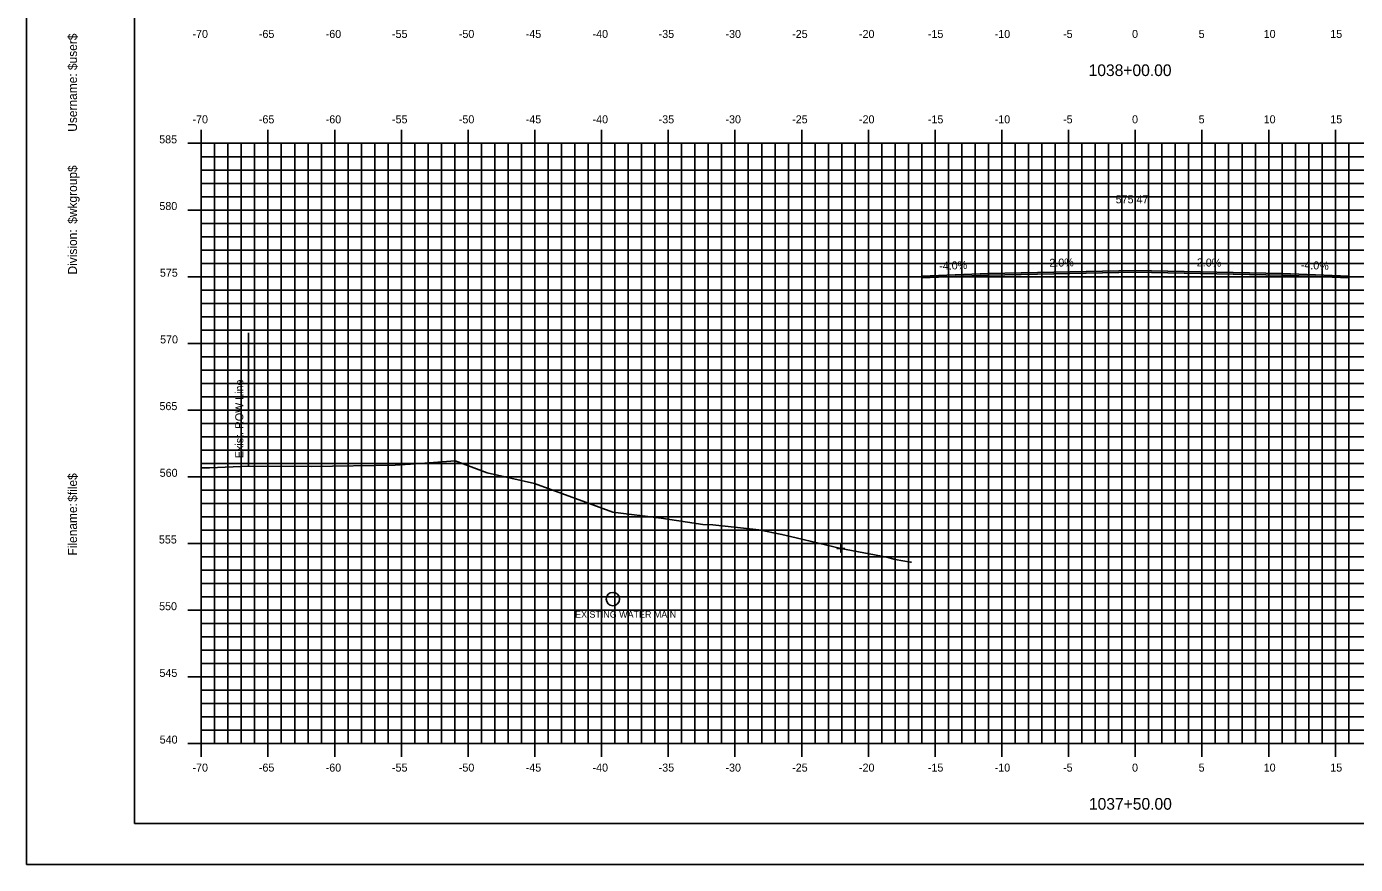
# Model space of a CAD drawing. Extents: x 1060781 to 1060951, y 779716 to 779826.
# Drawn here: x 1060780.7 to 1060880.3, y 779715.6 to 779778.5 of the extents above; entities that cross this region are included whole.
import ezdxf

# ---------------------------------------------------------------- set-up
doc = ezdxf.new("R2010")
doc.units = 0
for name, color, linetype in [('ANNOTATION', 7, 'Continuous'), ('BORDER', 7, 'Continuous'), ('D_Roadway_Centerline', 7, 'Continuous'), ('D_Roadway_Centerline_Text', 7, 'Continuous'), ('D_Roadway_Edge_TW_Mill_Overlay', 7, 'Continuous'), ('D_Text_Monospaced', 7, 'Continuous'), ('E_ROW_Line', 7, 'Continuous'), ('Existing Water Main', 7, 'Continuous'), ('H_V ANNOTATION', 7, 'Continuous'), ('MAJOR', 7, 'Continuous'), ('MINOR', 7, 'Continuous'), ('PLOT BOUNDARY', 7, 'Continuous'), ('S_Roadway_Centerline', 7, 'Continuous'), ('S_Wetland_RiverineUnconsSubstr', 7, 'Continuous')]:
    doc.layers.add(name, color=color, linetype=linetype)

msp = doc.modelspace()

# ---------------------------------------------------------------- linework, layer by layer
at = {"layer": 'BORDER'}
msp.add_lwpolyline([(1060788.836, 779718.706), (1060948.836, 779718.706), (1060948.836, 779823.706), (1060788.836, 779823.706)], close=True, dxfattribs=at)
at = {"layer": 'D_Roadway_Centerline'}
msp.add_lwpolyline([(1060847.836, 779759.756), (1060852.836, 779759.956), (1060863.836, 779760.176), (1060874.836, 779759.956), (1060879.836, 779759.756)], dxfattribs=at)
at = {"layer": 'D_Roadway_Edge_TW_Mill_Overlay'}
msp.add_lwpolyline([(1060863.836, 779760.176), (1060874.836, 779759.956), (1060879.836, 779759.756), (1060879.836, 779759.631), (1060874.836, 779759.831), (1060863.836, 779760.051), (1060852.836, 779759.831), (1060847.836, 779759.631), (1060847.836, 779759.756), (1060852.836, 779759.956)], close=True, dxfattribs=at)
at = {"layer": 'E_ROW_Line'}
msp.add_line((1060797.383, 779745.511), (1060797.383, 779755.511), dxfattribs=at)
msp.add_line((1060797.383, 779745.511), (1060797.383, 779755.511), dxfattribs=at)
at = {"layer": 'Existing Water Main'}
msp.add_lwpolyline([(1060824.687, 779735.541), (1060824.687, 779735.541)], dxfattribs=at)
msp.add_circle((1060824.687, 779735.541), 0.501, dxfattribs=at)
at = {"layer": 'MAJOR'}
for p, q in [((1060793.836, 779770.708), (1060793.836, 779769.706)), ((1060798.836, 779770.708), (1060798.836, 779769.706)), ((1060803.836, 779770.708), (1060803.836, 779769.706)), ((1060808.836, 779770.708), (1060808.836, 779769.706)), ((1060813.836, 779770.708), (1060813.836, 779769.706)), ((1060818.836, 779770.708), (1060818.836, 779769.706)), ((1060823.836, 779770.708), (1060823.836, 779769.706)), ((1060828.836, 779770.708), (1060828.836, 779769.706)), ((1060833.836, 779770.708), (1060833.836, 779769.706)), ((1060838.836, 779770.708), (1060838.836, 779769.706)), ((1060843.836, 779770.708), (1060843.836, 779769.706)), ((1060848.836, 779770.708), (1060848.836, 779769.706)), ((1060853.836, 779770.708), (1060853.836, 779769.706)), ((1060858.836, 779770.708), (1060858.836, 779769.706)), ((1060863.836, 779770.708), (1060863.836, 779769.706)), ((1060868.836, 779770.708), (1060868.836, 779769.706)), ((1060873.836, 779770.708), (1060873.836, 779769.706)), ((1060878.836, 779770.708), (1060878.836, 779769.706)), ((1060792.834, 779769.706), (1060793.836, 779769.706)), ((1060793.836, 779769.706), (1060933.836, 779769.706)), ((1060793.836, 779724.706), (1060793.836, 779769.706)), ((1060793.836, 779724.706), (1060793.836, 779769.706)), ((1060793.836, 779769.706), (1060933.836, 779769.706)), ((1060798.836, 779724.706), (1060798.836, 779769.706)), ((1060803.836, 779724.706), (1060803.836, 779769.706)), ((1060808.836, 779724.706), (1060808.836, 779769.706)), ((1060813.836, 779724.706), (1060813.836, 779769.706)), ((1060818.836, 779724.706), (1060818.836, 779769.706)), ((1060823.836, 779724.706), (1060823.836, 779769.706)), ((1060828.836, 779724.706), (1060828.836, 779769.706)), ((1060833.836, 779724.706), (1060833.836, 779769.706)), ((1060838.836, 779724.706), (1060838.836, 779769.706)), ((1060843.836, 779724.706), (1060843.836, 779769.706)), ((1060848.836, 779724.706), (1060848.836, 779769.706)), ((1060853.836, 779724.706), (1060853.836, 779769.706)), ((1060858.836, 779724.706), (1060858.836, 779769.706)), ((1060863.836, 779724.706), (1060863.836, 779769.706)), ((1060868.836, 779724.706), (1060868.836, 779769.706)), ((1060873.836, 779724.706), (1060873.836, 779769.706)), ((1060878.836, 779724.706), (1060878.836, 779769.706)), ((1060792.834, 779764.706), (1060793.836, 779764.706)), ((1060793.836, 779764.706), (1060933.836, 779764.706)), ((1060792.834, 779759.706), (1060793.836, 779759.706)), ((1060793.836, 779759.706), (1060933.836, 779759.706)), ((1060792.834, 779754.706), (1060793.836, 779754.706)), ((1060793.836, 779754.706), (1060933.836, 779754.706)), ((1060792.834, 779749.706), (1060793.836, 779749.706)), ((1060793.836, 779749.706), (1060933.836, 779749.706)), ((1060792.834, 779744.706), (1060793.836, 779744.706)), ((1060793.836, 779744.706), (1060933.836, 779744.706)), ((1060792.834, 779739.706), (1060793.836, 779739.706)), ((1060793.836, 779739.706), (1060933.836, 779739.706)), ((1060792.834, 779734.706), (1060793.836, 779734.706)), ((1060793.836, 779734.706), (1060933.836, 779734.706)), ((1060792.834, 779729.706), (1060793.836, 779729.706)), ((1060793.836, 779729.706), (1060933.836, 779729.706)), ((1060792.834, 779724.706), (1060793.836, 779724.706)), ((1060793.836, 779724.706), (1060933.836, 779724.706)), ((1060793.836, 779724.706), (1060933.836, 779724.706)), ((1060793.836, 779723.704), (1060793.836, 779724.706)), ((1060798.836, 779723.704), (1060798.836, 779724.706)), ((1060803.836, 779723.704), (1060803.836, 779724.706)), ((1060808.836, 779723.704), (1060808.836, 779724.706)), ((1060813.836, 779723.704), (1060813.836, 779724.706)), ((1060818.836, 779723.704), (1060818.836, 779724.706)), ((1060823.836, 779723.704), (1060823.836, 779724.706)), ((1060828.836, 779723.704), (1060828.836, 779724.706)), ((1060833.836, 779723.704), (1060833.836, 779724.706)), ((1060838.836, 779723.704), (1060838.836, 779724.706)), ((1060843.836, 779723.704), (1060843.836, 779724.706)), ((1060848.836, 779723.704), (1060848.836, 779724.706)), ((1060853.836, 779723.704), (1060853.836, 779724.706)), ((1060858.836, 779723.704), (1060858.836, 779724.706)), ((1060863.836, 779723.704), (1060863.836, 779724.706)), ((1060868.836, 779723.704), (1060868.836, 779724.706)), ((1060873.836, 779723.704), (1060873.836, 779724.706)), ((1060878.836, 779723.704), (1060878.836, 779724.706))]:
    msp.add_line(p, q, dxfattribs=at)
at = {"layer": 'MINOR'}
for p, q in [((1060794.836, 779724.706), (1060794.836, 779769.706)), ((1060795.836, 779724.706), (1060795.836, 779769.706)), ((1060796.836, 779724.706), (1060796.836, 779769.706)), ((1060797.836, 779724.706), (1060797.836, 779769.706)), ((1060799.836, 779724.706), (1060799.836, 779769.706)), ((1060800.836, 779724.706), (1060800.836, 779769.706)), ((1060801.836, 779724.706), (1060801.836, 779769.706)), ((1060802.836, 779724.706), (1060802.836, 779769.706)), ((1060804.836, 779724.706), (1060804.836, 779769.706)), ((1060805.836, 779724.706), (1060805.836, 779769.706)), ((1060806.836, 779724.706), (1060806.836, 779769.706)), ((1060807.836, 779724.706), (1060807.836, 779769.706)), ((1060809.836, 779724.706), (1060809.836, 779769.706)), ((1060810.836, 779724.706), (1060810.836, 779769.706)), ((1060811.836, 779724.706), (1060811.836, 779769.706)), ((1060812.836, 779724.706), (1060812.836, 779769.706)), ((1060814.836, 779724.706), (1060814.836, 779769.706)), ((1060815.836, 779724.706), (1060815.836, 779769.706)), ((1060816.836, 779724.706), (1060816.836, 779769.706)), ((1060817.836, 779724.706), (1060817.836, 779769.706)), ((1060819.836, 779724.706), (1060819.836, 779769.706)), ((1060820.836, 779724.706), (1060820.836, 779769.706)), ((1060821.836, 779724.706), (1060821.836, 779769.706)), ((1060822.836, 779724.706), (1060822.836, 779769.706)), ((1060824.836, 779724.706), (1060824.836, 779769.706)), ((1060825.836, 779724.706), (1060825.836, 779769.706)), ((1060826.836, 779724.706), (1060826.836, 779769.706)), ((1060827.836, 779724.706), (1060827.836, 779769.706)), ((1060829.836, 779724.706), (1060829.836, 779769.706)), ((1060830.836, 779724.706), (1060830.836, 779769.706)), ((1060831.836, 779724.706), (1060831.836, 779769.706)), ((1060832.836, 779724.706), (1060832.836, 779769.706)), ((1060834.836, 779724.706), (1060834.836, 779769.706)), ((1060835.836, 779724.706), (1060835.836, 779769.706)), ((1060836.836, 779724.706), (1060836.836, 779769.706)), ((1060837.836, 779724.706), (1060837.836, 779769.706)), ((1060839.836, 779724.706), (1060839.836, 779769.706)), ((1060840.836, 779724.706), (1060840.836, 779769.706)), ((1060841.836, 779724.706), (1060841.836, 779769.706)), ((1060842.836, 779724.706), (1060842.836, 779769.706)), ((1060844.836, 779724.706), (1060844.836, 779769.706)), ((1060845.836, 779724.706), (1060845.836, 779769.706)), ((1060846.836, 779724.706), (1060846.836, 779769.706)), ((1060847.836, 779724.706), (1060847.836, 779769.706)), ((1060849.836, 779724.706), (1060849.836, 779769.706)), ((1060850.836, 779724.706), (1060850.836, 779769.706)), ((1060851.836, 779724.706), (1060851.836, 779769.706)), ((1060852.836, 779724.706), (1060852.836, 779769.706)), ((1060854.836, 779724.706), (1060854.836, 779769.706)), ((1060855.836, 779724.706), (1060855.836, 779769.706)), ((1060856.836, 779724.706), (1060856.836, 779769.706)), ((1060857.836, 779724.706), (1060857.836, 779769.706)), ((1060859.836, 779724.706), (1060859.836, 779769.706)), ((1060860.836, 779724.706), (1060860.836, 779769.706)), ((1060861.836, 779724.706), (1060861.836, 779769.706)), ((1060862.836, 779724.706), (1060862.836, 779769.706)), ((1060864.836, 779724.706), (1060864.836, 779769.706)), ((1060865.836, 779724.706), (1060865.836, 779769.706)), ((1060866.836, 779724.706), (1060866.836, 779769.706)), ((1060867.836, 779724.706), (1060867.836, 779769.706)), ((1060869.836, 779724.706), (1060869.836, 779769.706)), ((1060870.836, 779724.706), (1060870.836, 779769.706)), ((1060871.836, 779724.706), (1060871.836, 779769.706)), ((1060872.836, 779724.706), (1060872.836, 779769.706)), ((1060874.836, 779724.706), (1060874.836, 779769.706)), ((1060875.836, 779724.706), (1060875.836, 779769.706)), ((1060876.836, 779724.706), (1060876.836, 779769.706)), ((1060877.836, 779724.706), (1060877.836, 779769.706)), ((1060879.836, 779724.706), (1060879.836, 779769.706)), ((1060793.836, 779768.706), (1060933.836, 779768.706)), ((1060793.836, 779768.706), (1060794.838, 779768.706)), ((1060793.836, 779767.706), (1060933.836, 779767.706)), ((1060793.836, 779767.706), (1060794.838, 779767.706)), ((1060793.836, 779766.706), (1060933.836, 779766.706)), ((1060793.836, 779766.706), (1060794.838, 779766.706)), ((1060793.836, 779765.706), (1060933.836, 779765.706)), ((1060793.836, 779765.706), (1060794.838, 779765.706)), ((1060793.836, 779763.706), (1060933.836, 779763.706)), ((1060793.836, 779763.706), (1060794.838, 779763.706)), ((1060793.836, 779762.706), (1060933.836, 779762.706)), ((1060793.836, 779762.706), (1060794.838, 779762.706)), ((1060793.836, 779761.706), (1060933.836, 779761.706)), ((1060793.836, 779761.706), (1060794.838, 779761.706)), ((1060793.836, 779760.706), (1060933.836, 779760.706)), ((1060793.836, 779760.706), (1060794.838, 779760.706)), ((1060793.836, 779758.706), (1060933.836, 779758.706)), ((1060793.836, 779758.706), (1060794.838, 779758.706)), ((1060793.836, 779757.706), (1060933.836, 779757.706)), ((1060793.836, 779757.706), (1060794.838, 779757.706)), ((1060793.836, 779756.706), (1060933.836, 779756.706)), ((1060793.836, 779756.706), (1060794.838, 779756.706)), ((1060793.836, 779755.706), (1060933.836, 779755.706)), ((1060793.836, 779755.706), (1060794.838, 779755.706)), ((1060793.836, 779753.706), (1060933.836, 779753.706)), ((1060793.836, 779753.706), (1060794.838, 779753.706)), ((1060793.836, 779752.706), (1060933.836, 779752.706)), ((1060793.836, 779752.706), (1060794.838, 779752.706)), ((1060793.836, 779751.706), (1060933.836, 779751.706)), ((1060793.836, 779751.706), (1060794.838, 779751.706)), ((1060793.836, 779750.706), (1060933.836, 779750.706)), ((1060793.836, 779750.706), (1060794.838, 779750.706)), ((1060793.836, 779748.706), (1060933.836, 779748.706)), ((1060793.836, 779748.706), (1060794.838, 779748.706)), ((1060793.836, 779747.706), (1060933.836, 779747.706)), ((1060793.836, 779747.706), (1060794.838, 779747.706)), ((1060793.836, 779746.706), (1060933.836, 779746.706)), ((1060793.836, 779746.706), (1060794.838, 779746.706)), ((1060793.836, 779745.706), (1060933.836, 779745.706)), ((1060793.836, 779745.706), (1060794.838, 779745.706)), ((1060793.836, 779743.706), (1060933.836, 779743.706)), ((1060793.836, 779743.706), (1060794.838, 779743.706)), ((1060793.836, 779742.706), (1060933.836, 779742.706)), ((1060793.836, 779742.706), (1060794.838, 779742.706)), ((1060793.836, 779741.706), (1060933.836, 779741.706)), ((1060793.836, 779741.706), (1060794.838, 779741.706)), ((1060793.836, 779740.706), (1060933.836, 779740.706)), ((1060793.836, 779740.706), (1060794.838, 779740.706)), ((1060793.836, 779738.706), (1060933.836, 779738.706)), ((1060793.836, 779738.706), (1060794.838, 779738.706)), ((1060793.836, 779737.706), (1060933.836, 779737.706)), ((1060793.836, 779737.706), (1060794.838, 779737.706)), ((1060793.836, 779736.706), (1060933.836, 779736.706)), ((1060793.836, 779736.706), (1060794.838, 779736.706)), ((1060793.836, 779735.706), (1060933.836, 779735.706)), ((1060793.836, 779735.706), (1060794.838, 779735.706)), ((1060793.836, 779733.706), (1060933.836, 779733.706)), ((1060793.836, 779733.706), (1060794.838, 779733.706)), ((1060793.836, 779732.706), (1060933.836, 779732.706)), ((1060793.836, 779732.706), (1060794.838, 779732.706)), ((1060793.836, 779731.706), (1060933.836, 779731.706)), ((1060793.836, 779731.706), (1060794.838, 779731.706)), ((1060793.836, 779730.706), (1060933.836, 779730.706)), ((1060793.836, 779730.706), (1060794.838, 779730.706)), ((1060793.836, 779728.706), (1060933.836, 779728.706)), ((1060793.836, 779728.706), (1060794.838, 779728.706)), ((1060793.836, 779727.706), (1060933.836, 779727.706)), ((1060793.836, 779727.706), (1060794.838, 779727.706)), ((1060793.836, 779726.706), (1060933.836, 779726.706)), ((1060793.836, 779726.706), (1060794.838, 779726.706)), ((1060793.836, 779725.706), (1060933.836, 779725.706)), ((1060793.836, 779725.706), (1060794.838, 779725.706))]:
    msp.add_line(p, q, dxfattribs=at)
at = {"layer": 'PLOT BOUNDARY'}
msp.add_lwpolyline([(1060780.743, 779715.646), (1060950.743, 779715.646), (1060950.743, 779825.646), (1060780.743, 779825.646)], close=True, dxfattribs=at)
at = {"layer": 'S_Roadway_Centerline'}
msp.add_lwpolyline([(1060793.836, 779745.391), (1060794.442, 779745.388), (1060797.393, 779745.511), (1060802.088, 779745.48), (1060808.374, 779745.584), (1060810.254, 779745.692), (1060812.875, 779745.908), (1060815.263, 779745.013), (1060818.818, 779744.197), (1060824.672, 779742.043), (1060828.314, 779741.607), (1060831.414, 779741.12), (1060832.174, 779741.1), (1060835.613, 779740.742), (1060837.355, 779740.393), (1060838.424, 779740.134), (1060841.777, 779739.342), (1060845.207, 779738.671), (1060845.85, 779738.508), (1060846.992, 779738.306), (1060847.066, 779738.306)], dxfattribs=at)
at = {"layer": 'S_Wetland_RiverineUnconsSubstr'}
msp.add_lwpolyline([(1060841.77, 779739.343), (1060841.77, 779739.643), (1060841.77, 779739.343), (1060841.47, 779739.343), (1060841.77, 779739.343), (1060841.77, 779739.043), (1060841.77, 779739.343), (1060842.07, 779739.343)], dxfattribs=at)

# ---------------------------------------------------------------- texts
at = {"layer": 'ANNOTATION'}
for s, rotation, p in [('-4.0%', 2.29061, (1060849.152, 779760.209)), ('-2.0%', 1.14576, (1060857.139, 779760.442)), ('-2.0%', 358.85424, (1060868.179, 779760.489)), ('-4.0%', 357.70939, (1060876.232, 779760.301))]:
    msp.add_text(s, height=0.6, rotation=rotation, dxfattribs=at).set_placement(p)
at = {"layer": 'BORDER'}
for s, p in [('$user$', (1060784.521, 779775.197)), ('Username:', (1060784.521, 779770.573)), ('$wkgroup$', (1060784.521, 779763.675)), ('Division:', (1060784.521, 779759.872)), ('$file$', (1060784.521, 779742.831)), ('Filename:', (1060784.521, 779738.804))]:
    msp.add_text(s, height=0.6696, rotation=90, dxfattribs=at).set_placement(p)
at = {"layer": 'D_Roadway_Centerline_Text'}
msp.add_text('575.47', height=0.6, dxfattribs=at).set_placement((1060862.37, 779765.208))
at = {"layer": 'D_Text_Monospaced'}
msp.add_text('EXISTING WATER MAIN', height=0.49998, dxfattribs=at).set_placement((1060821.853, 779734.141))
at = {"layer": 'E_ROW_Line'}
msp.add_text('Exist. ROW Line', height=0.6, rotation=90, dxfattribs=at).set_placement((1060796.983, 779746.111))
at = {"layer": 'H_V ANNOTATION'}
for s, height, p in [('-70', 0.6, (1060793.178, 779777.606)), ('-65', 0.6, (1060798.154, 779777.606)), ('-60', 0.6, (1060803.162, 779777.606)), ('-55', 0.6, (1060808.132, 779777.606)), ('-50', 0.6, (1060813.14, 779777.606)), ('-45', 0.6, (1060818.154, 779777.606)), ('-40', 0.6, (1060823.162, 779777.606)), ('-35', 0.6, (1060828.116, 779777.606)), ('-30', 0.6, (1060833.124, 779777.606)), ('-25', 0.6, (1060838.122, 779777.606)), ('-20', 0.6, (1060843.13, 779777.606)), ('-15', 0.6, (1060848.293, 779777.606)), ('-10', 0.6, (1060853.301, 779777.606)), ('-5', 0.6, (1060858.427, 779777.606)), ('0', 0.6, (1060863.595, 779777.606)), ('5', 0.6, (1060868.587, 779777.606)), ('10', 0.6, (1060873.461, 779777.606)), ('15', 0.6, (1060878.453, 779777.606)), ('1038+00.00', 0.875, (1060860.34, 779774.749)), ('-70', 0.6, (1060793.178, 779771.206)), ('-65', 0.6, (1060798.154, 779771.206)), ('-60', 0.6, (1060803.162, 779771.206)), ('-55', 0.6, (1060808.132, 779771.206)), ('-50', 0.6, (1060813.14, 779771.206)), ('-45', 0.6, (1060818.154, 779771.206)), ('-40', 0.6, (1060823.162, 779771.206)), ('-35', 0.6, (1060828.116, 779771.206)), ('-30', 0.6, (1060833.124, 779771.206)), ('-25', 0.6, (1060838.122, 779771.206)), ('-20', 0.6, (1060843.13, 779771.206)), ('-15', 0.6, (1060848.293, 779771.206)), ('-10', 0.6, (1060853.301, 779771.206)), ('-5', 0.6, (1060858.427, 779771.206)), ('0', 0.6, (1060863.595, 779771.206)), ('5', 0.6, (1060868.587, 779771.206)), ('10', 0.6, (1060873.461, 779771.206)), ('15', 0.6, (1060878.453, 779771.206)), ('585', 0.6, (1060790.682, 779769.706)), ('580', 0.6, (1060790.698, 779764.706)), ('575', 0.6, (1060790.735, 779759.706)), ('570', 0.6, (1060790.751, 779754.706)), ('565', 0.6, (1060790.703, 779749.706)), ('560', 0.6, (1060790.72, 779744.706)), ('555', 0.6, (1060790.66, 779739.706)), ('550', 0.6, (1060790.677, 779734.706)), ('545', 0.6, (1060790.703, 779729.706)), ('540', 0.6, (1060790.72, 779724.706)), ('-70', 0.6, (1060793.178, 779722.606)), ('-65', 0.6, (1060798.154, 779722.606)), ('-60', 0.6, (1060803.162, 779722.606)), ('-55', 0.6, (1060808.132, 779722.606)), ('-50', 0.6, (1060813.14, 779722.606)), ('-45', 0.6, (1060818.154, 779722.606)), ('-40', 0.6, (1060823.162, 779722.606)), ('-35', 0.6, (1060828.116, 779722.606)), ('-30', 0.6, (1060833.124, 779722.606)), ('-25', 0.6, (1060838.122, 779722.606)), ('-20', 0.6, (1060843.13, 779722.606)), ('-15', 0.6, (1060848.293, 779722.606)), ('-10', 0.6, (1060853.301, 779722.606)), ('-5', 0.6, (1060858.427, 779722.606)), ('0', 0.6, (1060863.595, 779722.606)), ('5', 0.6, (1060868.587, 779722.606)), ('10', 0.6, (1060873.461, 779722.606)), ('15', 0.6, (1060878.453, 779722.606)), ('1037+50.00', 0.875, (1060860.364, 779719.749))]:
    msp.add_text(s, height=height, dxfattribs=at).set_placement(p)
at = {"layer": 'MAJOR'}
msp.add_text('-', height=0.006, dxfattribs=at).set_placement((1060793.832, 779724.706))

doc.saveas('drawing.dxf')
